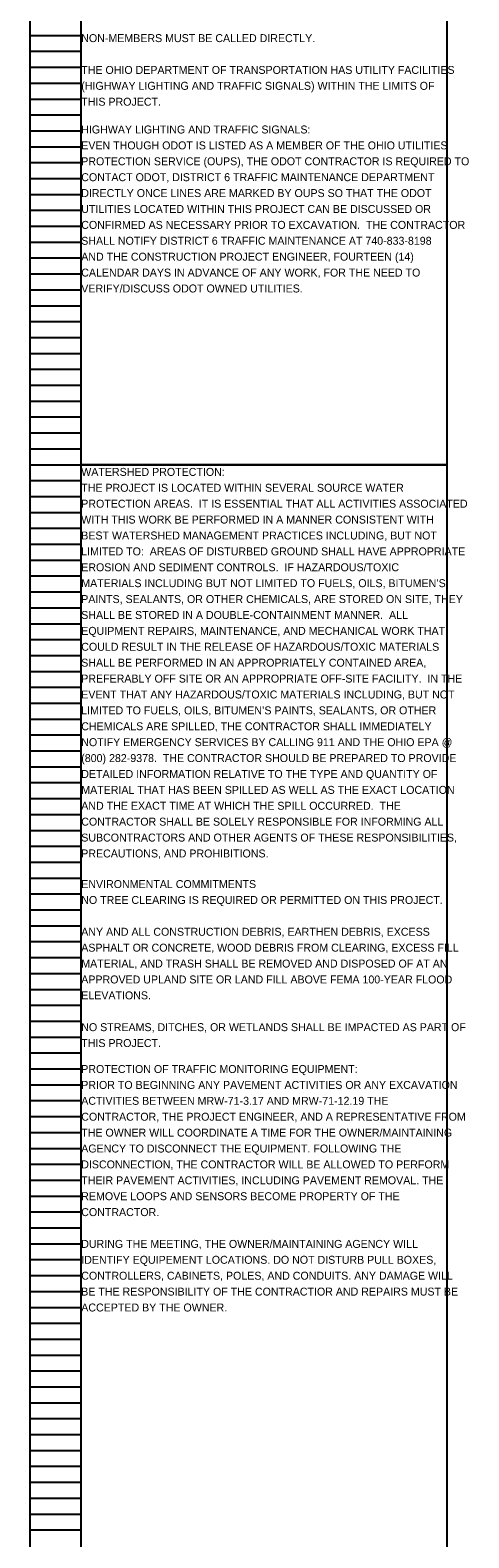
# Model space of a CAD drawing. Extents: x 16463 to 16500, y 5400 to 5823.
# Drawn here: x 16463.05 to 16470.77, y 5744.09 to 5770.64 of the extents above; entities that cross this region are included whole.
import ezdxf

# ---------------------------------------------------------------- set-up
doc = ezdxf.new("R2010")
doc.units = 0
for name, color, linetype in [('Default', 7, 'Continuous'), ('SC_Scratch1', 7, 'Continuous'), ('SH_Data', 7, 'Continuous')]:
    doc.layers.add(name, color=color, linetype=linetype)

msp = doc.modelspace()

# ---------------------------------------------------------------- linework, layer by layer
at = {"layer": 'SC_Scratch1'}
for points in [[(16463.949, 5783.152), (16470.389, 5783.152), (16470.389, 5762.992), (16463.949, 5762.992)], [(16463.949, 5762.992), (16470.389, 5762.992), (16470.389, 5742.832), (16463.949, 5742.832)]]:
    msp.add_lwpolyline(points, close=True, dxfattribs=at)
at = {"layer": 'SH_Data'}
for p, q in [((16463.049, 5762.992), (16463.049, 5783.152)), ((16463.949, 5762.992), (16463.949, 5783.152)), ((16463.049, 5770.552), (16463.949, 5770.552)), ((16463.049, 5770.272), (16463.949, 5770.272)), ((16463.049, 5769.992), (16463.949, 5769.992)), ((16463.049, 5769.712), (16463.949, 5769.712)), ((16463.049, 5769.432), (16463.949, 5769.432)), ((16463.049, 5769.152), (16463.949, 5769.152)), ((16463.049, 5768.872), (16463.949, 5768.872)), ((16463.049, 5768.592), (16463.949, 5768.592)), ((16463.049, 5768.312), (16463.949, 5768.312)), ((16463.049, 5768.032), (16463.949, 5768.032)), ((16463.049, 5767.752), (16463.949, 5767.752)), ((16463.049, 5767.472), (16463.949, 5767.472)), ((16463.049, 5767.192), (16463.949, 5767.192)), ((16463.049, 5766.912), (16463.949, 5766.912)), ((16463.049, 5766.632), (16463.949, 5766.632)), ((16463.049, 5766.352), (16463.949, 5766.352)), ((16463.049, 5766.072), (16463.949, 5766.072)), ((16463.049, 5765.792), (16463.949, 5765.792)), ((16463.049, 5765.512), (16463.949, 5765.512)), ((16463.049, 5765.232), (16463.949, 5765.232)), ((16463.049, 5764.952), (16463.949, 5764.952)), ((16463.049, 5764.672), (16463.949, 5764.672)), ((16463.049, 5764.392), (16463.949, 5764.392)), ((16463.049, 5764.112), (16463.949, 5764.112)), ((16463.049, 5763.832), (16463.949, 5763.832)), ((16463.049, 5763.552), (16463.949, 5763.552)), ((16463.049, 5763.272), (16463.949, 5763.272)), ((16463.049, 5742.832), (16463.049, 5762.992)), ((16463.049, 5762.992), (16463.949, 5762.992)), ((16463.049, 5762.992), (16463.949, 5762.992)), ((16463.949, 5742.832), (16463.949, 5762.992)), ((16463.049, 5762.712), (16463.949, 5762.712)), ((16463.049, 5762.432), (16463.949, 5762.432)), ((16463.049, 5762.152), (16463.949, 5762.152)), ((16463.049, 5761.872), (16463.949, 5761.872)), ((16463.049, 5761.592), (16463.949, 5761.592)), ((16463.049, 5761.312), (16463.949, 5761.312)), ((16463.049, 5761.032), (16463.949, 5761.032)), ((16463.049, 5760.752), (16463.949, 5760.752)), ((16463.049, 5760.472), (16463.949, 5760.472)), ((16463.049, 5760.192), (16463.949, 5760.192)), ((16463.049, 5759.912), (16463.949, 5759.912)), ((16463.049, 5759.632), (16463.949, 5759.632)), ((16463.049, 5759.352), (16463.949, 5759.352)), ((16463.049, 5759.072), (16463.949, 5759.072)), ((16463.049, 5758.792), (16463.949, 5758.792)), ((16463.049, 5758.512), (16463.949, 5758.512)), ((16463.049, 5758.232), (16463.949, 5758.232)), ((16463.049, 5757.952), (16463.949, 5757.952)), ((16463.049, 5757.672), (16463.949, 5757.672)), ((16463.049, 5757.392), (16463.949, 5757.392)), ((16463.049, 5757.112), (16463.949, 5757.112)), ((16463.049, 5756.832), (16463.949, 5756.832)), ((16463.049, 5756.552), (16463.949, 5756.552)), ((16463.049, 5756.272), (16463.949, 5756.272)), ((16463.049, 5755.992), (16463.949, 5755.992)), ((16463.049, 5755.712), (16463.949, 5755.712)), ((16463.049, 5755.432), (16463.949, 5755.432)), ((16463.049, 5755.152), (16463.949, 5755.152)), ((16463.049, 5754.872), (16463.949, 5754.872)), ((16463.049, 5754.592), (16463.949, 5754.592)), ((16463.049, 5754.312), (16463.949, 5754.312)), ((16463.049, 5754.032), (16463.949, 5754.032)), ((16463.049, 5753.752), (16463.949, 5753.752)), ((16463.049, 5753.472), (16463.949, 5753.472)), ((16463.049, 5753.192), (16463.949, 5753.192)), ((16463.049, 5752.912), (16463.949, 5752.912)), ((16463.049, 5752.632), (16463.949, 5752.632)), ((16463.049, 5752.352), (16463.949, 5752.352)), ((16463.049, 5752.072), (16463.949, 5752.072)), ((16463.049, 5751.792), (16463.949, 5751.792)), ((16463.049, 5751.512), (16463.949, 5751.512)), ((16463.049, 5751.232), (16463.949, 5751.232)), ((16463.049, 5750.952), (16463.949, 5750.952)), ((16463.049, 5750.672), (16463.949, 5750.672)), ((16463.049, 5750.392), (16463.949, 5750.392)), ((16463.049, 5750.112), (16463.949, 5750.112)), ((16463.049, 5749.832), (16463.949, 5749.832)), ((16463.049, 5749.552), (16463.949, 5749.552)), ((16463.049, 5749.272), (16463.949, 5749.272)), ((16463.049, 5748.992), (16463.949, 5748.992)), ((16463.049, 5748.712), (16463.949, 5748.712)), ((16463.049, 5748.432), (16463.949, 5748.432)), ((16463.049, 5748.152), (16463.949, 5748.152)), ((16463.049, 5747.872), (16463.949, 5747.872)), ((16463.049, 5747.592), (16463.949, 5747.592)), ((16463.049, 5747.312), (16463.949, 5747.312)), ((16463.049, 5747.032), (16463.949, 5747.032)), ((16463.049, 5746.752), (16463.949, 5746.752)), ((16463.049, 5746.472), (16463.949, 5746.472)), ((16463.049, 5746.192), (16463.949, 5746.192)), ((16463.049, 5745.912), (16463.949, 5745.912)), ((16463.049, 5745.632), (16463.949, 5745.632)), ((16463.049, 5745.352), (16463.949, 5745.352)), ((16463.049, 5745.072), (16463.949, 5745.072)), ((16463.049, 5744.792), (16463.949, 5744.792)), ((16463.049, 5744.512), (16463.949, 5744.512)), ((16463.049, 5744.232), (16463.949, 5744.232))]:
    msp.add_line(p, q, dxfattribs=at)

# ---------------------------------------------------------------- texts
at = {"layer": 'Default'}
for s, p in [('NON-MEMBERS MUST BE CALLED DIRECTLY.', (16463.949, 5770.434)), ('THE OHIO DEPARTMENT OF TRANSPORTATION HAS UTILITY FACILITIES ', (16463.949, 5769.874)), ('(HIGHWAY LIGHTING AND TRAFFIC SIGNALS) WITHIN THE LIMITS OF ', (16463.949, 5769.594)), ('THIS PROJECT.', (16463.949, 5769.314)), ('HIGHWAY LIGHTING AND TRAFFIC SIGNALS:', (16463.949, 5768.825)), ('EVEN THOUGH ODOT IS LISTED AS A MEMBER OF THE OHIO UTILITIES ', (16463.949, 5768.545)), ('PROTECTION SERVICE (OUPS), THE ODOT CONTRACTOR IS REQUIRED TO ', (16463.949, 5768.265)), ('CONTACT ODOT, DISTRICT 6 TRAFFIC MAINTENANCE DEPARTMENT ', (16463.949, 5767.985)), ('DIRECTLY ONCE LINES ARE MARKED BY OUPS SO THAT THE ODOT ', (16463.949, 5767.705)), ('UTILITIES LOCATED WITHIN THIS PROJECT CAN BE DISCUSSED OR ', (16463.949, 5767.425)), ('CONFIRMED AS NECESSARY PRIOR TO EXCAVATION.  THE CONTRACTOR ', (16463.949, 5767.145)), ('SHALL NOTIFY DISTRICT 6 TRAFFIC MAINTENANCE AT 740-833-8198 ', (16463.949, 5766.865)), ('AND THE CONSTRUCTION PROJECT ENGINEER, FOURTEEN (14) ', (16463.949, 5766.585)), ('CALENDAR DAYS IN ADVANCE OF ANY WORK, FOR THE NEED TO ', (16463.949, 5766.305)), ('VERIFY/DISCUSS ODOT OWNED UTILITIES.', (16463.949, 5766.025)), ('WATERSHED PROTECTION:', (16463.949, 5762.795)), ('THE PROJECT IS LOCATED WITHIN SEVERAL SOURCE WATER ', (16463.949, 5762.515)), ('PROTECTION AREAS.  IT IS ESSENTIAL THAT ALL ACTIVITIES ASSOCIATED ', (16463.949, 5762.235)), ('WITH THIS WORK BE PERFORMED IN A MANNER CONSISTENT WITH ', (16463.949, 5761.955)), ('BEST WATERSHED MANAGEMENT PRACTICES INCLUDING, BUT NOT ', (16463.949, 5761.675)), ('LIMITED TO:  AREAS OF DISTURBED GROUND SHALL HAVE APPROPRIATE ', (16463.949, 5761.395)), ('EROSION AND SEDIMENT CONTROLS.  IF HAZARDOUS/TOXIC ', (16463.949, 5761.115)), ('MATERIALS INCLUDING BUT NOT LIMITED TO FUELS, OILS, BITUMEN’S ', (16463.949, 5760.835)), ('PAINTS, SEALANTS, OR OTHER CHEMICALS, ARE STORED ON SITE, THEY ', (16463.949, 5760.555)), ('SHALL BE STORED IN A DOUBLE-CONTAINMENT MANNER.  ALL ', (16463.949, 5760.275)), ('EQUIPMENT REPAIRS, MAINTENANCE, AND MECHANICAL WORK THAT ', (16463.949, 5759.995)), ('COULD RESULT IN THE RELEASE OF HAZARDOUS/TOXIC MATERIALS ', (16463.949, 5759.715)), ('SHALL BE PERFORMED IN AN APPROPRIATELY CONTAINED AREA, ', (16463.949, 5759.435)), ('PREFERABLY OFF SITE OR AN APPROPRIATE OFF-SITE FACILITY.  IN THE ', (16463.949, 5759.155)), ('EVENT THAT ANY HAZARDOUS/TOXIC MATERIALS INCLUDING, BUT NOT ', (16463.949, 5758.875)), ('LIMITED TO FUELS, OILS, BITUMEN’S PAINTS, SEALANTS, OR OTHER ', (16463.949, 5758.595)), ('CHEMICALS ARE SPILLED, THE CONTRACTOR SHALL IMMEDIATELY ', (16463.949, 5758.315)), ('NOTIFY EMERGENCY SERVICES BY CALLING 911 AND THE OHIO EPA @ ', (16463.949, 5758.035)), ('(800) 282-9378.  THE CONTRACTOR SHOULD BE PREPARED TO PROVIDE ', (16463.949, 5757.755)), ('DETAILED INFORMATION RELATIVE TO THE TYPE AND QUANTITY OF ', (16463.949, 5757.475)), ('MATERIAL THAT HAS BEEN SPILLED AS WELL AS THE EXACT LOCATION ', (16463.949, 5757.195)), ('AND THE EXACT TIME AT WHICH THE SPILL OCCURRED.  THE ', (16463.949, 5756.915)), ('CONTRACTOR SHALL BE SOLELY RESPONSIBLE FOR INFORMING ALL ', (16463.949, 5756.635)), ('SUBCONTRACTORS AND OTHER AGENTS OF THESE RESPONSIBILITIES, ', (16463.949, 5756.355)), ('PRECAUTIONS, AND PROHIBITIONS.', (16463.949, 5756.075)), ('ENVIRONMENTAL COMMITMENTS', (16463.949, 5755.536)), ('NO TREE CLEARING IS REQUIRED OR PERMITTED ON THIS PROJECT.', (16463.949, 5755.256)), ('ANY AND ALL CONSTRUCTION DEBRIS, EARTHEN DEBRIS, EXCESS ', (16463.949, 5754.696)), ('ASPHALT OR CONCRETE, WOOD DEBRIS FROM CLEARING, EXCESS FILL ', (16463.949, 5754.416)), ('MATERIAL, AND TRASH SHALL BE REMOVED AND DISPOSED OF AT AN ', (16463.949, 5754.136)), ('APPROVED UPLAND SITE OR LAND FILL ABOVE FEMA 100-YEAR FLOOD ', (16463.949, 5753.856)), ('ELEVATIONS.', (16463.949, 5753.576)), ('NO STREAMS, DITCHES, OR WETLANDS SHALL BE IMPACTED AS PART OF ', (16463.949, 5753.016)), ('THIS PROJECT.', (16463.949, 5752.736)), ('PROTECTION OF TRAFFIC MONITORING EQUIPMENT:', (16463.949, 5752.279)), ('PRIOR TO BEGINNING ANY PAVEMENT ACTIVITIES OR ANY EXCAVATION ', (16463.949, 5751.999)), ('ACTIVITIES BETWEEN MRW-71-3.17 AND MRW-71-12.19 THE ', (16463.949, 5751.719)), ('CONTRACTOR, THE PROJECT ENGINEER, AND A REPRESENTATIVE FROM ', (16463.949, 5751.439)), ('THE OWNER WILL COORDINATE A TIME FOR THE OWNER/MAINTAINING ', (16463.949, 5751.159)), ('AGENCY TO DISCONNECT THE EQUIPMENT. FOLLOWING THE ', (16463.949, 5750.879)), ('DISCONNECTION, THE CONTRACTOR WILL BE ALLOWED TO PERFORM ', (16463.949, 5750.599)), ('THEIR PAVEMENT ACTIVITIES, INCLUDING PAVEMENT REMOVAL. THE ', (16463.949, 5750.319)), ('REMOVE LOOPS AND SENSORS BECOME PROPERTY OF THE ', (16463.949, 5750.039)), ('CONTRACTOR.', (16463.949, 5749.759)), ('DURING THE MEETING, THE OWNER/MAINTAINING AGENCY WILL ', (16463.949, 5749.199)), ('IDENTIFY EQUIPEMENT LOCATIONS. DO NOT DISTURB PULL BOXES, ', (16463.949, 5748.919)), ('CONTROLLERS, CABINETS, POLES, AND CONDUITS. ANY DAMAGE WILL ', (16463.949, 5748.639)), ('BE THE RESPONSIBILITY OF THE CONTRACTIOR AND REPAIRS MUST BE ', (16463.949, 5748.359)), ('ACCEPTED BY THE OWNER.', (16463.949, 5748.079))]:
    msp.add_text(s, height=0.14, dxfattribs=at).set_placement(p)

doc.saveas('drawing.dxf')
